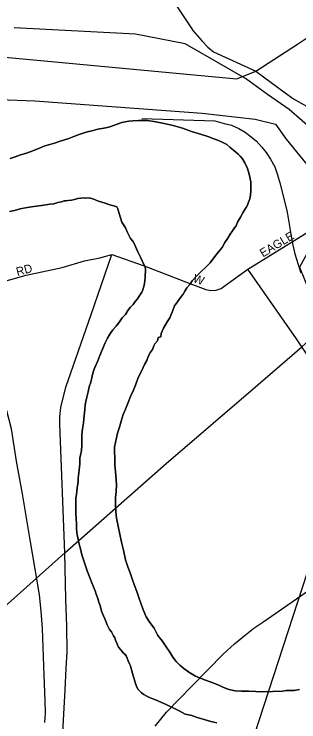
# Model space of a CAD drawing. Extents: x -561 to 1170, y 0 to 846.
# Drawn here: x 240.77 to 245.33, y 275.8 to 287.14 of the extents above; entities that cross this region are included whole.
import ezdxf

# ---------------------------------------------------------------- set-up
doc = ezdxf.new("R2010")
doc.units = 0
for name, color, linetype in [('GM_X_City_Street', 7, 'Continuous'), ('GM_X_City_Street_Text', 7, 'Continuous'), ('GM_X_Interstate_Route', 7, 'Continuous'), ('GM_X_Major_River', 7, 'Continuous'), ('GM_X_Rail_Line', 7, 'Continuous'), ('GM_X_State_Route', 7, 'Continuous'), ('GM_X_US_Route', 7, 'Continuous')]:
    doc.layers.add(name, color=color, linetype=linetype)

msp = doc.modelspace()

# ---------------------------------------------------------------- linework, layer by layer
at = {"layer": 'GM_X_City_Street'}
for points in [[(245.311, 286.658), (245.489, 286.774), (245.532, 286.805)], [(238.444, 286.651), (244.34, 286.102), (244.643, 286.223)], [(244.643, 286.223), (245.311, 286.658)], [(238.12, 284.963), (238.728, 285.393), (240.111, 285.69), (240.526, 285.769), (241.099, 285.749), (243.786, 285.552), (244.635, 285.453), (244.96, 285.373), (245.133, 285.135), (245.606, 284.554), (245.658, 284.393), (245.745, 283.808), (245.346, 283.081), (245.504, 282.686), (245.785, 282.171), (246.097, 281.579), (246.779, 280.673), (248.07, 278.955)], [(243.585, 282.824), (243.841, 282.725), (243.924, 282.711), (244.01, 282.713), (244.087, 282.743), (244.154, 282.789), (244.517, 283.051), (245.745, 283.808), (247.019, 284.791)], [(239.934, 282.664), (240.962, 282.953), (241.537, 283.08), (241.9, 283.186), (242.146, 283.231), (242.335, 283.286)], [(241.587, 270.54), (241.581, 270.976), (241.449, 272.588), (241.4, 272.851), (241.47, 274.167), (241.587, 276.31), (241.601, 276.652), (241.62, 276.918), (241.615, 277.331), (241.596, 277.763), (241.582, 278.503), (241.5, 280.566), (241.5, 280.686), (241.519, 280.834), (241.598, 281.16), (242.005, 282.324), (242.335, 283.286)], [(242.335, 283.286), (242.855, 283.106), (243.585, 282.824)], [(245.979, 280.839), (245.969, 280.891), (245.905, 281.043), (245.383, 281.806), (245.295, 281.933), (244.517, 283.051)]]:
    msp.add_lwpolyline(points, dxfattribs=at)
at = {"layer": 'GM_X_Interstate_Route'}
msp.add_lwpolyline([(243.658, 272.569), (244.153, 274.175), (244.255, 274.474), (244.387, 274.865), (245.71, 278.914), (245.891, 279.295)], dxfattribs=at)
at = {"layer": 'GM_X_Major_River'}
for points in [[(243.973, 283.235), (244.047, 283.328), (244.106, 283.399), (244.148, 283.476), (244.196, 283.547), (244.233, 283.612), (244.27, 283.667), (244.302, 283.711), (244.329, 283.743), (244.349, 283.803), (244.397, 283.885), (244.434, 283.956), (244.466, 284.005), (244.492, 284.038), (244.514, 284.076), (244.529, 284.125), (244.55, 284.18), (244.56, 284.239), (244.565, 284.304), (244.564, 284.369), (244.563, 284.451), (244.539, 284.575), (244.511, 284.667), (244.466, 284.753), (244.433, 284.817), (244.394, 284.86), (244.362, 284.892), (244.318, 284.93), (244.268, 284.972), (244.23, 285.005), (244.181, 285.047), (244.105, 285.084), (244.045, 285.111), (243.974, 285.142), (243.876, 285.179), (243.756, 285.216), (243.615, 285.257), (243.468, 285.31), (243.321, 285.351), (243.175, 285.387), (243.039, 285.413), (242.909, 285.433), (242.763, 285.436), (242.676, 285.43), (242.606, 285.424), (242.552, 285.412), (242.498, 285.401), (242.304, 285.333), (242.239, 285.316), (242.175, 285.305), (242.11, 285.293), (242.034, 285.271), (241.926, 285.248), (241.862, 285.225), (241.797, 285.203), (241.727, 285.175), (241.646, 285.147), (241.56, 285.119), (241.49, 285.096), (241.414, 285.073), (241.344, 285.051), (241.264, 285.028), (241.188, 284.995), (241.07, 284.95), (240.967, 284.911), (240.87, 284.883), (240.784, 284.849), (240.703, 284.826)], [(240.703, 284.826), (240.784, 284.849), (240.87, 284.883), (240.967, 284.911), (241.07, 284.95), (241.188, 284.995), (241.264, 285.028), (241.344, 285.051), (241.414, 285.073), (241.49, 285.096), (241.56, 285.119), (241.646, 285.147), (241.727, 285.175), (241.797, 285.203), (241.862, 285.225), (241.926, 285.248), (242.034, 285.271), (242.11, 285.293), (242.175, 285.305), (242.239, 285.316), (242.304, 285.333), (242.498, 285.401), (242.552, 285.412), (242.606, 285.424), (242.676, 285.43), (242.763, 285.436), (242.909, 285.433), (243.039, 285.413), (243.175, 285.387), (243.321, 285.351), (243.468, 285.31), (243.615, 285.257), (243.756, 285.216), (243.876, 285.179), (243.974, 285.142), (244.045, 285.111), (244.105, 285.084), (244.181, 285.047), (244.23, 285.005), (244.268, 284.972), (244.318, 284.93), (244.362, 284.892), (244.394, 284.86), (244.433, 284.817), (244.466, 284.753), (244.511, 284.667), (244.539, 284.575), (244.563, 284.451), (244.564, 284.369), (244.565, 284.304), (244.56, 284.239), (244.55, 284.18), (244.529, 284.125), (244.514, 284.076), (244.492, 284.038), (244.466, 284.005), (244.434, 283.956), (244.397, 283.885), (244.349, 283.803), (244.329, 283.743), (244.302, 283.711), (244.27, 283.667), (244.233, 283.612), (244.196, 283.547), (244.148, 283.476), (244.106, 283.399), (244.047, 283.328), (243.973, 283.235)], [(240.693, 283.976), (240.774, 283.993), (240.866, 284.016), (240.979, 284.039), (241.087, 284.056), (241.206, 284.074), (241.341, 284.092), (241.406, 284.098), (241.471, 284.121), (241.53, 284.132), (241.573, 284.144), (241.6, 284.144), (241.638, 284.15), (241.687, 284.156), (241.735, 284.167), (241.789, 284.184)], [(241.789, 284.184), (241.735, 284.167), (241.687, 284.156), (241.638, 284.15), (241.6, 284.144), (241.573, 284.144), (241.53, 284.132), (241.471, 284.121), (241.406, 284.098), (241.341, 284.092), (241.206, 284.074), (241.087, 284.056), (240.979, 284.039), (240.866, 284.016), (240.774, 283.993), (240.693, 283.976)], [(241.789, 284.184), (241.838, 284.19), (241.887, 284.196), (241.914, 284.191), (241.962, 284.192), (241.995, 284.187), (242.033, 284.176), (242.071, 284.16), (242.12, 284.139), (242.174, 284.124), (242.229, 284.108), (242.272, 284.092), (242.321, 284.077), (242.37, 284.067), (242.414, 284.051), (242.43, 284.018), (242.453, 283.943), (242.498, 283.803), (242.554, 283.711), (242.587, 283.641), (242.637, 283.544), (242.67, 283.501), (242.698, 283.453), (242.715, 283.415), (242.731, 283.377), (242.754, 283.329), (242.776, 283.286), (242.793, 283.243), (242.821, 283.183), (242.843, 283.135), (242.865, 283.097), (242.877, 283.054), (242.877, 283.016), (242.872, 282.957), (242.868, 282.919), (242.863, 282.864), (242.858, 282.821), (242.848, 282.772), (242.832, 282.718), (242.817, 282.68), (242.774, 282.62), (242.748, 282.576), (242.71, 282.532), (242.679, 282.483), (242.631, 282.439), (242.593, 282.39), (242.556, 282.324), (242.503, 282.269), (242.461, 282.209), (242.407, 282.138), (242.354, 282.078), (242.306, 282.012), (242.264, 281.947), (242.227, 281.871), (242.143, 281.669), (242.112, 281.582), (242.065, 281.473), (242.038, 281.408), (242.018, 281.337), (241.997, 281.239), (241.971, 281.163), (241.956, 281.087), (241.936, 281), (241.921, 280.93), (241.91, 280.875), (241.901, 280.8), (241.891, 280.707), (241.882, 280.588), (241.867, 280.49), (241.857, 280.398), (241.853, 280.328), (241.854, 280.279), (241.854, 280.225), (241.85, 280.143), (241.835, 280.073), (241.825, 280.024), (241.825, 279.975), (241.821, 279.932), (241.816, 279.883), (241.811, 279.829), (241.806, 279.785), (241.801, 279.747), (241.797, 279.704), (241.797, 279.655), (241.792, 279.606), (241.782, 279.552), (241.772, 279.492), (241.768, 279.438), (241.758, 279.384), (241.758, 279.335), (241.759, 279.265), (241.76, 279.205), (241.761, 279.135), (241.762, 279.053), (241.769, 278.972), (241.77, 278.902), (241.776, 278.826), (241.788, 278.745), (241.805, 278.664), (241.834, 278.567), (241.857, 278.475)], [(241.857, 278.475), (241.834, 278.567), (241.805, 278.664), (241.788, 278.745), (241.776, 278.826), (241.77, 278.902), (241.769, 278.972), (241.762, 279.053), (241.761, 279.135), (241.76, 279.205), (241.759, 279.265), (241.758, 279.335), (241.758, 279.384), (241.768, 279.438), (241.772, 279.492), (241.782, 279.552), (241.792, 279.606), (241.797, 279.655), (241.797, 279.704), (241.801, 279.747), (241.806, 279.785), (241.811, 279.829), (241.816, 279.883), (241.821, 279.932), (241.825, 279.975), (241.825, 280.024), (241.835, 280.073), (241.85, 280.143), (241.854, 280.225), (241.854, 280.279), (241.853, 280.328), (241.857, 280.398), (241.867, 280.49), (241.882, 280.588), (241.891, 280.707), (241.901, 280.8), (241.91, 280.875), (241.921, 280.93), (241.936, 281), (241.956, 281.087), (241.971, 281.163), (241.997, 281.239), (242.018, 281.337), (242.038, 281.408), (242.065, 281.473), (242.112, 281.582), (242.143, 281.669), (242.227, 281.871), (242.264, 281.947), (242.306, 282.012), (242.354, 282.078), (242.407, 282.138), (242.461, 282.209), (242.503, 282.269), (242.556, 282.324), (242.593, 282.39), (242.631, 282.439), (242.679, 282.483), (242.71, 282.532), (242.748, 282.576), (242.774, 282.62), (242.817, 282.68), (242.832, 282.718), (242.848, 282.772), (242.858, 282.821), (242.863, 282.864), (242.868, 282.919), (242.872, 282.957), (242.877, 283.016), (242.877, 283.054), (242.865, 283.097), (242.843, 283.135), (242.821, 283.183), (242.793, 283.243), (242.776, 283.286), (242.754, 283.329), (242.731, 283.377), (242.715, 283.415), (242.698, 283.453), (242.67, 283.501), (242.637, 283.544), (242.587, 283.641), (242.554, 283.711), (242.498, 283.803), (242.453, 283.943), (242.43, 284.018), (242.414, 284.051), (242.37, 284.067), (242.321, 284.077), (242.272, 284.092), (242.229, 284.108), (242.174, 284.124), (242.12, 284.139), (242.071, 284.16), (242.033, 284.176), (241.995, 284.187), (241.962, 284.192), (241.914, 284.191), (241.887, 284.196), (241.838, 284.19), (241.789, 284.184)], [(245.345, 276.317), (245.259, 276.3), (245.188, 276.299), (245.134, 276.299), (245.07, 276.287), (244.756, 276.278), (244.647, 276.282), (244.534, 276.286), (244.414, 276.29), (244.312, 276.294), (244.241, 276.31), (244.198, 276.32), (244.159, 276.336), (244.116, 276.351), (244.051, 276.383), (243.958, 276.42), (243.795, 276.478), (243.675, 276.53), (243.571, 276.594), (243.489, 276.653), (243.424, 276.706), (243.369, 276.765), (243.314, 276.835), (243.264, 276.915), (243.209, 277.001), (243.142, 277.093), (243.076, 277.179), (243.015, 277.297), (242.943, 277.388), (242.888, 277.48), (242.843, 277.582), (242.804, 277.685), (242.77, 277.787), (242.736, 277.884), (242.697, 277.981), (242.663, 278.089), (242.629, 278.186), (242.59, 278.283), (242.556, 278.391), (242.522, 278.548), (242.493, 278.678), (242.464, 278.802), (242.435, 278.932), (242.412, 279.061), (242.399, 279.169), (242.392, 279.283), (242.396, 279.392), (242.406, 279.489), (242.41, 279.587), (242.403, 279.679), (242.396, 279.803), (242.384, 279.917), (242.382, 280.025), (242.381, 280.123), (242.38, 280.199), (242.425, 280.421), (242.457, 280.519), (242.488, 280.617), (242.519, 280.72), (242.556, 280.807), (242.597, 280.916), (242.634, 281.009), (242.676, 281.101), (242.713, 281.194), (242.76, 281.314), (242.818, 281.428), (242.86, 281.521), (242.897, 281.586), (242.917, 281.652), (242.954, 281.722), (242.986, 281.766), (243.007, 281.821), (243.023, 281.853), (243.066, 281.902), (243.081, 281.957), (243.119, 281.968), (243.129, 282.022), (243.166, 282.104), (243.224, 282.208), (243.266, 282.273), (243.287, 282.322), (243.303, 282.36), (243.318, 282.404), (243.339, 282.464), (243.387, 282.529), (243.424, 282.579), (243.451, 282.617), (243.478, 282.65), (243.509, 282.699), (243.541, 282.753), (243.584, 282.803), (243.626, 282.863), (243.695, 282.939), (243.914, 283.153), (243.973, 283.235)], [(243.973, 283.235), (243.914, 283.153), (243.695, 282.939), (243.626, 282.863), (243.584, 282.803), (243.541, 282.753), (243.509, 282.699), (243.478, 282.65), (243.451, 282.617), (243.424, 282.579), (243.387, 282.529), (243.339, 282.464), (243.318, 282.404), (243.303, 282.36), (243.287, 282.322), (243.266, 282.273), (243.224, 282.208), (243.166, 282.104), (243.129, 282.022), (243.119, 281.968), (243.081, 281.957), (243.066, 281.902), (243.023, 281.853), (243.007, 281.821), (242.986, 281.766), (242.954, 281.722), (242.917, 281.652), (242.897, 281.586), (242.86, 281.521), (242.818, 281.428), (242.76, 281.314), (242.713, 281.194), (242.676, 281.101), (242.634, 281.009), (242.597, 280.916), (242.556, 280.807), (242.519, 280.72), (242.488, 280.617), (242.457, 280.519), (242.425, 280.421), (242.38, 280.199), (242.381, 280.123), (242.382, 280.025), (242.384, 279.917), (242.396, 279.803), (242.403, 279.679), (242.41, 279.587), (242.406, 279.489), (242.396, 279.392), (242.392, 279.283), (242.399, 279.169), (242.412, 279.061), (242.435, 278.932), (242.464, 278.802), (242.493, 278.678), (242.522, 278.548), (242.556, 278.391), (242.59, 278.283), (242.629, 278.186), (242.663, 278.089), (242.697, 277.981), (242.736, 277.884), (242.77, 277.787), (242.804, 277.685), (242.843, 277.582), (242.888, 277.48), (242.943, 277.388), (243.015, 277.297), (243.076, 277.179), (243.142, 277.093), (243.209, 277.001), (243.264, 276.915), (243.314, 276.835), (243.369, 276.765), (243.424, 276.706), (243.489, 276.653), (243.571, 276.594), (243.675, 276.53), (243.795, 276.478), (243.958, 276.42), (244.051, 276.383), (244.116, 276.351), (244.159, 276.336), (244.198, 276.32), (244.241, 276.31), (244.312, 276.294), (244.414, 276.29), (244.534, 276.286), (244.647, 276.282), (244.756, 276.278), (245.07, 276.287), (245.134, 276.299), (245.188, 276.299), (245.259, 276.3), (245.345, 276.317)], [(241.857, 278.475), (241.879, 278.394), (241.913, 278.297), (241.941, 278.216), (242.014, 278.027), (242.042, 277.962), (242.07, 277.898), (242.087, 277.844), (242.11, 277.774), (242.127, 277.714), (242.149, 277.66), (242.172, 277.569), (242.2, 277.498), (242.223, 277.445), (242.245, 277.396), (242.262, 277.353), (242.279, 277.321), (242.301, 277.278), (242.328, 277.24), (242.345, 277.208), (242.362, 277.175), (242.384, 277.143), (242.395, 277.105), (242.417, 277.057), (242.429, 277.03), (242.445, 276.992), (242.478, 276.949), (242.517, 276.901), (242.544, 276.88), (242.566, 276.853), (242.583, 276.815), (242.6, 276.777), (242.617, 276.729), (242.633, 276.696), (242.639, 276.669), (242.662, 276.599), (242.673, 276.551), (242.69, 276.502), (242.707, 276.448), (242.719, 276.394), (242.736, 276.351), (242.758, 276.313), (242.813, 276.26), (242.851, 276.233), (242.895, 276.207), (242.949, 276.18), (243.009, 276.159), (243.074, 276.133), (243.134, 276.107), (243.205, 276.075), (243.428, 275.969), (243.51, 275.922), (243.619, 275.896), (243.706, 275.864), (243.814, 275.833), (243.923, 275.802), (244.021, 275.781)], [(244.021, 275.781), (243.923, 275.802), (243.814, 275.833), (243.706, 275.864), (243.619, 275.896), (243.51, 275.922), (243.428, 275.969), (243.205, 276.075), (243.134, 276.107), (243.074, 276.133), (243.009, 276.159), (242.949, 276.18), (242.895, 276.207), (242.851, 276.233), (242.813, 276.26), (242.758, 276.313), (242.736, 276.351), (242.719, 276.394), (242.707, 276.448), (242.69, 276.502), (242.673, 276.551), (242.662, 276.599), (242.639, 276.669), (242.633, 276.696), (242.617, 276.729), (242.6, 276.777), (242.583, 276.815), (242.566, 276.853), (242.544, 276.88), (242.517, 276.901), (242.478, 276.949), (242.445, 276.992), (242.429, 277.03), (242.417, 277.057), (242.395, 277.105), (242.384, 277.143), (242.362, 277.175), (242.345, 277.208), (242.328, 277.24), (242.301, 277.278), (242.279, 277.321), (242.262, 277.353), (242.245, 277.396), (242.223, 277.445), (242.2, 277.498), (242.172, 277.569), (242.149, 277.66), (242.127, 277.714), (242.11, 277.774), (242.087, 277.844), (242.07, 277.898), (242.042, 277.962), (242.014, 278.027), (241.941, 278.216), (241.913, 278.297), (241.879, 278.394), (241.857, 278.475)]]:
    msp.add_lwpolyline(points, dxfattribs=at)
at = {"layer": 'GM_X_Rail_Line'}
for points in [[(254.889, 279.009), (254.125, 279.424), (253.349, 279.891), (252.637, 280.316), (251.278, 281.092), (249.026, 282.495), (248.144, 283.036), (247.602, 283.387), (247.05, 283.823), (246.646, 284.184), (246.041, 284.779), (245.595, 285.247), (245.181, 285.608), (244.83, 285.852), (244.479, 286.107), (243.513, 286.66), (242.716, 286.819), (240.769, 286.918)], [(242.815, 285.463), (243.986, 285.426), (244.135, 285.388), (244.253, 285.357), (244.375, 285.304), (244.474, 285.249), (244.571, 285.173), (244.655, 285.1), (244.742, 285.005), (244.811, 284.923), (244.881, 284.815), (244.948, 284.691), (244.994, 284.563), (245.032, 284.432), (245.072, 284.27), (245.146, 283.965), (245.208, 283.612), (245.238, 283.434), (245.271, 283.297), (245.322, 283.124), (245.368, 282.992)], [(241.224, 277.293), (241.205, 277.568), (241.175, 277.834), (241.107, 278.244), (241.02, 278.744), (240.901, 279.449), (240.806, 279.973), (240.728, 280.495), (240.575, 281.068), (239.975, 282.291), (239.235, 283.608), (238.376, 284.763)], [(243.21, 275.951), (243.617, 276.368), (244.127, 276.885), (244.302, 277.045), (244.477, 277.192), (244.612, 277.299), (244.756, 277.395), (245.629, 278), (246.254, 278.429), (246.406, 278.532), (246.541, 278.608), (246.692, 278.687), (246.832, 278.756), (246.97, 278.812), (247.314, 278.942), (248.128, 279.27)], [(241.263, 275.787), (241.272, 275.934), (241.268, 276.131), (241.249, 276.545), (241.224, 277.293)], [(243.03, 275.725), (243.21, 275.951)]]:
    msp.add_lwpolyline(points, dxfattribs=at)
at = {"layer": 'GM_X_State_Route'}
msp.add_lwpolyline([(239.547, 276.691), (241.582, 278.503), (243.205, 279.937), (244.675, 281.198), (245.383, 281.806), (245.785, 282.171), (246.707, 282.968)], dxfattribs=at)
at = {"layer": 'GM_X_US_Route'}
for points in [[(243.232, 287.484), (243.619, 286.905)], [(243.619, 286.905), (243.637, 286.878), (243.785, 286.705), (243.876, 286.609), (243.967, 286.535), (244.643, 286.223), (245.115, 285.878)], [(245.115, 285.878), (245.25, 285.779), (245.998, 285.361)]]:
    msp.add_lwpolyline(points, dxfattribs=at)

# ---------------------------------------------------------------- texts
at = {"layer": 'GM_X_City_Street_Text'}
for s, rotation, p in [('EAGLE', 31.1382, (244.759, 283.237)), ('RD', 14.7447, (240.821, 282.942)), ('W', 341.5596, (243.628, 282.847))]:
    msp.add_text(s, height=0.135, rotation=rotation, dxfattribs=at).set_placement(p)

doc.saveas('drawing.dxf')
